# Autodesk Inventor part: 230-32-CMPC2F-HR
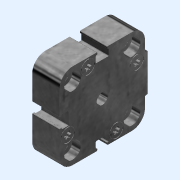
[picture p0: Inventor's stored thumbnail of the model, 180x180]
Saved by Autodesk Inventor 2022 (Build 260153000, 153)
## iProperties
Category: PARTsolutions
Company: METALWORK
Part Number: 230-32-CMPC2F-HR
Material: Generico
Catalog Web Link: www.cadenas.de
Description: CMPC2F-HR-
Vendor: METALWORK
Document SubType Name: Modeling
Designer: partserver
Manufacturer: METALWORK
Mass: 26.9446 g
Surface Area: 92.4817 cm^2
Volume: 26.9446 cm^3
Density: 1 g/cm^3
Appearance: Acciaio galvanizzato
PSOL_IDENT_0: {$CADENAS_DATA\23d-libs\metalwork\actuators\comp_cyl_ser_cmpc_2_flat\parts\cmpc_2_flat_head_rear.prj
PSOL_IDENT_1: },186 {VTYP=3D},{NB=230-32-CMPC2F-HR},{LINA=230-32-CMPC2F-HR},{NN=CMPC2F-HR},{DATE=18.06.2021 08:06:
PSOL_IDENT_2: 07},{GEOMDATE=26.11.2009 08:19:00},{VERSION=},{LINEID=50},{WBVAR=TYPE,VE},{WBNUMERIC=TYPE}  {NB=230-
PSOL_IDENT_3: 32-CMPC2F-HR},{LINA=230-32-CMPC2F-HR},{KT=DUMMY},{IDNR=},{DI=32},{TYPE=23},{VE=0},{A=46.300},{B=32.2
PSOL_IDENT_4: 50},{B2=0.000},{C=12.000},{D=47.800},{D1=9.000},{D2=7.600},{D3=7.000},{E=6.000},{H=7.500},{H1=6.950}
PSOL_IDENT_5: ,{H2=5.400},{H3=14.750},{H4=2.800},{L=4.500},{L1=3.700},{L2=1.200},{L3=10.000},{LD=1.700},{O=6.000},
PSOL_IDENT_6: {Q=9.728},{R1=7.150},{R2=3.400},{R3=0.300},{R4=0.500},{SW=0.000},{X=18.700},{Y=7.700},{TPL=230}
NB: 230-32-CMPC2F-HR
NN: CMPC2F-HR
NBSYN: $TPL.-$DI.-CMPC2F-HR
LINA: 230-32-CMPC2F-HR
CATALOG: Metalwork
DI: 32
TYPE: Centre distance to UNITOP, male rod
VE: Double-acting
A: 46.3
B: 32.25
B2: 0
C: 12
D: 47.8
D2: 7.6
D3: 7
E: 6
H: 7.5
H1: 6.95
H2: 5.4
H3: 14.75
H4: 2.8
L1: 3.7
L2: 1.2
L3: 10
LD: 1.7
O: 6
Q: 9.728
R1: 7.15
R2: 3.4
R3: 0.3
R4: 0.5
SW: 0
X: 18.7
Y: 7.7
SUPPLIER: METALWORK
ARTICLENO: 230-32-CMPC2F-HR
BOMINFO: 230-32-CMPC2F-HR
CREATOR: CADENAS GmbH
Title: 230-32-CMPC2F-HR
Author: Cadenas PARTsolutions
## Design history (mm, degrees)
sketch "Sketch_1"
  geometry: L1 (-23.15, 16)-(-23.15, 3.1); L2 (-22.75, 2.7)-(-22.15, 2.7); L3 (-21.95, 2.9)-(-21.95, 3.075); L4 (-21.55, 3.475)-(-18.65, 3.475); L5 (-18.25, 3.075)-(-18.25, -3.075); L6 (-18.65, -3.475)-(-21.55, -3.475); L7 (-21.95, -3.075)-(-21.95, -2.9); L8 (-22.15, -2.7)-(-22.75, -2.7); L9 (-23.15, -3.1)-(-23.15, -16); L10 (-16, -23.15)-(-3.1, -23.15); L11 (-2.7, -22.75)-(-2.7, -22.15); L12 (-2.9, -21.95)-(-3.075, -21.95); L13 (-3.475, -21.55)-(-3.475, -18.65); L14 (-3.075, -18.25)-(3.075, -18.25); L15 (3.475, -18.65)-(3.475, -21.55); L16 (3.075, -21.95)-(2.9, -21.95); L17 (2.7, -22.15)-(2.7, -22.75); L18 (3.1, -23.15)-(16, -23.15); L19 (23.15, -16)-(23.15, -10.402); L20 (23.15, -10.402)-(24.65, -10); L21 (24.65, -10)-(24.65, 10); L22 (24.65, 10)-(23.15, 10.402); L23 (23.15, 10.402)-(23.15, 16); L24 (16, 23.15)-(3.1, 23.15); L25 (2.7, 22.75)-(2.7, 22.15); L26 (2.9, 21.95)-(3.075, 21.95); L27 (3.475, 21.55)-(3.475, 18.65); L28 (3.075, 18.25)-(-3.075, 18.25); L29 (-3.475, 18.65)-(-3.475, 21.55); L30 (-3.075, 21.95)-(-2.9, 21.95); L31 (-2.7, 22.15)-(-2.7, 22.75); L32 (-3.1, 23.15)-(-16, 23.15); A1 r 7.15 centre (-16, 16) between (-16, 23.15) and (-23.15, 16); A2 r 0.4 centre (-22.75, 3.1) between (-23.15, 3.1) and (-22.75, 2.7); A3 r 0.2 centre (-22.15, 2.9) between (-22.15, 2.7) and (-21.95, 2.9); A4 r 0.4 centre (-21.55, 3.075) between (-21.55, 3.475) and (-21.95, 3.075); A5 r 0.4 centre (-18.65, 3.075) between (-18.25, 3.075) and (-18.65, 3.475); A6 r 0.4 centre (-18.65, -3.075) between (-18.65, -3.475) and (-18.25, -3.075); A7 r 0.4 centre (-21.55, -3.075) between (-21.95, -3.075) and (-21.55, -3.475); A8 r 0.2 centre (-22.15, -2.9) between (-21.95, -2.9) and (-22.15, -2.7); A9 r 0.4 centre (-22.75, -3.1) between (-22.75, -2.7) and (-23.15, -3.1); A10 r 7.15 centre (-16, -16) between (-23.15, -16) and (-16, -23.15); A11 r 0.4 centre (-3.1, -22.75) between (-3.1, -23.15) and (-2.7, -22.75); A12 r 0.2 centre (-2.9, -22.15) between (-2.7, -22.15) and (-2.9, -21.95); A13 r 0.4 centre (-3.075, -21.55) between (-3.475, -21.55) and (-3.075, -21.95); A14 r 0.4 centre (-3.075, -18.65) between (-3.075, -18.25) and (-3.475, -18.65); A15 r 0.4 centre (3.075, -18.65) between (3.475, -18.65) and (3.075, -18.25); A16 r 0.4 centre (3.075, -21.55) between (3.075, -21.95) and (3.475, -21.55); A17 r 0.2 centre (2.9, -22.15) between (2.9, -21.95) and (2.7, -22.15); A18 r 0.4 centre (3.1, -22.75) between (2.7, -22.75) and (3.1, -23.15); A19 r 7.15 centre (16, -16) between (16, -23.15) and (23.15, -16); A20 r 7.15 centre (16, 16) between (23.15, 16) and (16, 23.15); A21 r 0.4 centre (3.1, 22.75) between (3.1, 23.15) and (2.7, 22.75); A22 r 0.2 centre (2.9, 22.15) between (2.7, 22.15) and (2.9, 21.95); A23 r 0.4 centre (3.075, 21.55) between (3.475, 21.55) and (3.075, 21.95); A24 r 0.4 centre (3.075, 18.65) between (3.075, 18.25) and (3.475, 18.65); A25 r 0.4 centre (-3.075, 18.65) between (-3.475, 18.65) and (-3.075, 18.25); A26 r 0.4 centre (-3.075, 21.55) between (-3.075, 21.95) and (-3.475, 21.55); A27 r 0.2 centre (-2.9, 22.15) between (-2.9, 21.95) and (-2.7, 22.15); A28 r 0.4 centre (-3.1, 22.75) between (-2.7, 22.75) and (-3.1, 23.15)
  constraints: 64 end point, 56 point on circle, 28 centre point
extrude "Extrusion1" join sketch "Sketch_1" distance "d0" = 14.75; taper "d1" = 0 deg
sketch "Sketch2"
  geometry: 1 further point
hole "Hole1" sketch "Sketch2" at (7.5, 10) diameter "d2" = 8.566; stored, may be unused: countersink angle "d6" = 90 deg, drill point angle "d8" = 120 deg; dims "d3" = 9.728, "d4" = 4, "d5" = 2, "d7" = 14.592
sketch "Sketch_7"
  geometry: L1 (14.75, -16.125)-(0, -16.125); L2 (0, -16.125)-(0, -11.625); L3 (0, -11.625)-(4.5, -11.625); L4 (4.5, -11.625)-(4.5, -13.666); L5 (4.5, -13.666)-(14.75, -13.666); L6 (14.75, -13.666)-(14.75, -16.125); L7 (14.75, -16.125)-(0, -16.125)
  constraints: 14 end point
revolve "Revolution1" sketch "Sketch_7" stored, may be unused: angle "d9" = 360 deg
thread "Thread1" dims "d10" = 10.25, "d11" = 0
pattern_linear "Rectangular Pattern1" dims "d14" = 32.25, "d17" = 32.25
sketch "Sketch_13"
  geometry: C1 r 3.8 at (-18.7, 7.7); C2 r 3.5 at (-18.7, 7.7); 2 further points
  constraints: 2 centre point
extrude "Extrusion2" cut sketch "Sketch_13" distance "d18" = 2.8; taper "d19" = 0 deg
pattern_linear "Rectangular Pattern2" dims "d22" = 28.6, "d25" = 28.6
sketch "Sketch_19"
  geometry: L1 (-18.062, 9.384)-(-18.346, 9.1); L2 (-19.054, 9.1)-(-19.338, 9.384); L3 (-19.84, 9.095)-(-19.736, 8.706); L4 (-20.089, 8.094)-(-20.478, 7.99); L5 (-20.478, 7.41)-(-20.089, 7.306); L6 (-19.736, 6.694)-(-19.84, 6.305); L7 (-19.338, 6.016)-(-19.054, 6.3); L8 (-18.346, 6.3)-(-18.062, 6.016); L9 (-17.56, 6.305)-(-17.664, 6.694); L10 (-17.311, 7.306)-(-16.922, 7.41); L11 (-16.922, 7.99)-(-17.311, 8.094); L12 (-17.664, 8.706)-(-17.56, 9.095); A1 r 0.3 centre (-17.85, 9.172) between (-17.56, 9.095) and (-18.062, 9.384); A2 r 0.5 centre (-18.7, 9.454) between (-19.054, 9.1) and (-18.346, 9.1); A3 r 0.3 centre (-19.55, 9.172) between (-19.338, 9.384) and (-19.84, 9.095); A4 r 0.5 centre (-20.219, 8.577) between (-20.089, 8.094) and (-19.736, 8.706); A5 r 0.3 centre (-20.4, 7.7) between (-20.478, 7.99) and (-20.478, 7.41); A6 r 0.5 centre (-20.219, 6.823) between (-19.736, 6.694) and (-20.089, 7.306); A7 r 0.3 centre (-19.55, 6.228) between (-19.84, 6.305) and (-19.338, 6.016); A8 r 0.5 centre (-18.7, 5.946) between (-18.346, 6.3) and (-19.054, 6.3); A9 r 0.3 centre (-17.85, 6.228) between (-18.062, 6.016) and (-17.56, 6.305); A10 r 0.5 centre (-17.181, 6.823) between (-17.311, 7.306) and (-17.664, 6.694); A11 r 0.3 centre (-17, 7.7) between (-16.922, 7.41) and (-16.922, 7.99); A12 r 0.5 centre (-17.181, 8.577) between (-17.664, 8.706) and (-17.311, 8.094)
  constraints: 24 end point, 24 point on circle, 12 centre point
extrude "Extrusion3" cut sketch "Sketch_19" distance "d26" = 1.7; taper "d27" = 0 deg
pattern_linear "Rectangular Pattern3" dims "d30" = 28.6, "d33" = 28.6
sketch "Sketch6"
  geometry: 1 further point
hole "Hole2" sketch "Sketch6" at (0, 0) diameter "d34" = 6; stored, may be unused: countersink angle "d38" = 90 deg, drill point angle "d40" = 0 deg; dims "d35" = 6, "d36" = 4, "d37" = 2, "d39" = 4
node "accessories_XY"
node "accessories_YZ"
node "accessories_ZX"
node "accessories_X"
node "accessories_Y"
node "accessories_Z"
node "accessories_Center"
node "head_r_XY"
node "head_r_YZ"
node "head_r_ZX"
node "head_r_X"
node "head_r_Y"
node "head_r_Z"
node "head_r_Center"
body "Solid1"
other parameters: "d41" = 0, "d42" = 0
